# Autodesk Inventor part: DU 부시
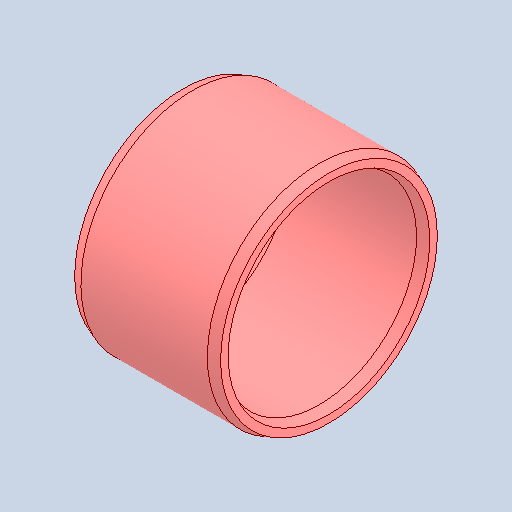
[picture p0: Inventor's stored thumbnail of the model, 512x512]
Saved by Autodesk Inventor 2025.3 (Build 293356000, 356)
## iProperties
Created: 2025-10
Part Number: DU 부시
Material: 스테인리스스틸
Document SubType Name: Modeling
Designer: PC-04
Density: 8 g/cm^3
Appearance: 기본값
Author: jhkim
Sending System: Autodesk Inventor 2026
Preprocessor: ST-DEVELOPER v20.1
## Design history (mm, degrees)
feature "솔리드1"
node "솔리드2"
